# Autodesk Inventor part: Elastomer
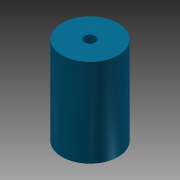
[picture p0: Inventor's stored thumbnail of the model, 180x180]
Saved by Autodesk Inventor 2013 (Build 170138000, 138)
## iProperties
Shininess: 64.0
Length Units: 11272
Angle Units: 11279
Time Units: 11290
Mass Units: 11286
Length Display Precision: 3
Angle Display Precision: 2
Compacted: True
Created: 2001-11
Part Number: Elastomer
Document SubType Name: Modeling
Designer: Autodesk, Inc.
Mass: 3.41477 g
Surface Area: 15.0056 cm^2
Volume: 3.41477 cm^3
Density: 1 g/cm^3
Material: Generic
Density: 0.0
Volumn: 0.0
Area: 0.0
PropertySet Name: Model Information
Control State: 0
Master: False
Checked Out: False
Author: Autodesk, Inc.
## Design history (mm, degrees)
sketch "Sketch1"
  geometry: L1 (144.661, 147.973)-(150.376, 147.973); L2 (150.376, 147.973)-(150.376, 125.621); L3 (150.376, 125.621)-(144.661, 125.621); L4 (144.661, 147.973)-(144.661, 125.621); L5 (143.264, 91.328)-(143.264, 147.973); L6 (143.264, 91.328)-(143.264, 147.973)
  constraints: 12 end point, 3 vertical, 2 horizontal, 1 other
  dimensions: "d1" = 22.352 distance of L1.end L2.end; "d3" = 7.112 distance of L5.end L1.end
revolve "RevolutionFull1" sketch "Sketch1" stored, may be unused: angle "d4" = 360 deg
body "Solid1"
other parameters: "d0" = 22.352 (derived), "d2" = 7.112 (derived)
